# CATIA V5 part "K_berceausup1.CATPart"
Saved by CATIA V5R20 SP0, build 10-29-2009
Part number: berceausup1
Bounding box of the stored display mesh (mm): x -13.5 to 13.5, y 95 to 105, z 38.01 to 61.99
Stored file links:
  G:\Khaled_CFAO_2011\SIL\SIL_GR2\mdupuis\Khaled\CAD_ThinkMOTION\K_berceausup1.CATPart
  G:\Dupuis_Maxime_Thinkmotion_CFAO\assemblage.CATProduct
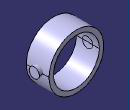
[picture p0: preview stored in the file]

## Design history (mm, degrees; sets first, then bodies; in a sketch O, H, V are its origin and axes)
External parameters (linked from other documents)
  External.diametrelunette = 20 mm
Set1
  Plane1: linked copy from another document
Body1 (main body)
  Sketch1 on Plane1, origin (0, 100, 0), H (-1, 0, 0), V (0, 0, 1)
    circle A1 centre (0, 50) radius 10
    circle A2 centre (0, 50) radius 12
    radius A1 = 10 {= External.diametrelunette /2}
    radius A2 = 12 {= External.diametrelunette /2 + 2mm}
  Pad1: profile Sketch1, direction (0, 1, 0), length 5, opposite side length 5
  Plane2: type Offset, RefPlane end face of Pad1, Offset 5
  Plane3: type Angle, RefPlane Plane2, Direction Z axis, Angle 90
  Point1: type Center, Curve edge [end face of Pad1 | face of Pad1 from Sketch1.A1]
  Point2: (0, -5, 0), relative to Point1
  Plane4: type OffsetPt, RefPlane Plane3, RefPoint Point2
  Sketch2 on Plane4, origin (0, 0, 0), H (0, 1, 0), V (0, 0, 1)
    circle A1 centre (100, 50) radius 2.2361
    point P1 (100, 50)
    reference projected point E1 (100, 50) from Point2
    distance P1 E1 = 0
  Extract1: ExtractElem face of Pad1 from Sketch1.A1
Body2
  Pad2: profile Sketch2, direction (1, 0, 0), length 13.5, mirrored extent
  Split1: SplitPlane Extract1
